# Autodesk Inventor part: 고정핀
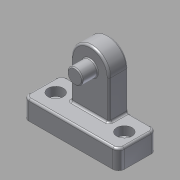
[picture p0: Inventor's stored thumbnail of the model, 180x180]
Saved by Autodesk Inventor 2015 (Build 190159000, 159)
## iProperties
Created: 2017-07
Part Number: 고정핀
Material: 알루미늄 6061
Document SubType Name: Modeling
Designer: mduedu
Density: 2.71 g/cm^3
Appearance: 알루미늄 - 평지
Mass: 41.2292 g
Surface Area: 53.4313 cm^2
Volume: 15.2137 cm^3
Author: mduedu
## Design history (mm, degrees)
sketch "스케치1"
  geometry: L1 (-25, 0)-(25, 0); L2 (-25, 10)-(25, 10); L3 (-25, 0)-(-25, 10); L4 (25, 0)-(25, 10); L5 (-10, 10)-(10, 10); L6 (10, 10)-(10, 40); L7 (10, 40)-(-10, 40); L8 (-10, 40)-(-10, 10); 3 further points
  constraints: 16 end point, 4 parallel, 2 horizontal, 2 midpoint, 2 perpendicular, 1 coincident, 1 point on line, 1 vertical alignment
  dimensions: "d0" = 50 distance of L1.start L1.end; "d2" = 10 distance of L1.end L2.end; "d3" = 20 distance of L6.end L7.end; "d4" = 40 distance between parallel lines of L7 L1
extrude "돌출1" new body sketch "스케치1" stored distance "d5" = 20; taper "d6" = 0 deg
extrude "돌출2" join sketch "스케치1" distance "d7" = 10; taper "d8" = 0 deg
fillet "모깎기1"
sketch "스케치2"
  geometry: C1 r 4 at (0, 30); A1 r 10 centre (0, 30) between (10, 30) and (-10, 30) reference; 1 further point
  constraints: 1 centre point, 1 coincident
  dimensions: "d9" = 8 diameter of C1
extrude "돌출3" join sketch "스케치2" distance "d10" = 8; taper "d11" = 0 deg
fillet "모깎기2" dims "d12" = 0.5
fillet "모깎기3" dims "d13" = 1
fillet "모깎기4" dims "d14" = 1
fillet "모깎기5" dims "d15" = 3
fillet "모깎기6" dims "d16" = 1
chamfer "모따기1" distance "d18" = 0.5; stored, may be unused: second distance "d19" = 2, angle "d20" = 45 deg
sketch "스케치3"
  geometry: L1 (-16, 8)-(-16, -6) reference; L2 (34, -6)-(34, 8) reference; L3 (-16, 1)-(34, 1); L4 (-13, -9)-(31, -9) reference; L5 (9, 1)-(9, -9); 2 further points
  constraints: 4 end point, 3 midpoint, 1 point on line, 1 symmetric about line
  dimensions: "d21" = 7 distance from line of point (-9, 1) L1
sketch "스케치4"
  geometry: L1 (-16, 1)-(34, 1) reference; L2 (9, 1)-(9, -9) reference; 7 further points
  constraints: 2 coincident
hole "구멍1" sketch "스케치4" at (27, 1), (-9, 1) diameter "d22" = 4.5; stored, may be unused: countersink angle "d26" = 90 deg, drill point angle "d28" = 0 deg; dims "d23" = 6, "d24" = 8, "d25" = 4.6, "d27" = 8
node "솔리드1"
